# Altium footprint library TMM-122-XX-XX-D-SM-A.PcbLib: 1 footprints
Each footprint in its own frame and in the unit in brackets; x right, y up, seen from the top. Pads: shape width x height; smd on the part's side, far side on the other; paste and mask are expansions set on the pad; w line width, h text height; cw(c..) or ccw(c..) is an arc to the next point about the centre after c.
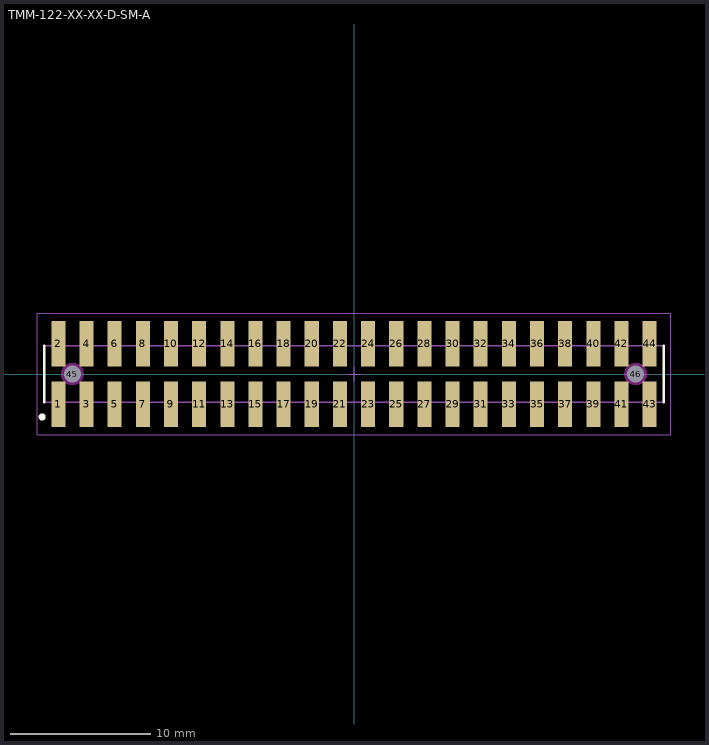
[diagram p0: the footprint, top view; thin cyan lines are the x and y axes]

## TMM-122-XX-XX-D-SM-A [mm] "2.00mm pitch, 44 pin, terminal strip; double row, w/alignment pins, SMT"
height 2.77
pads (46):
  rect 1x3.2 smd mask+0: 1(-21,-2.15) 2(-21,2.15) 3(-19,-2.15) 4(-19,2.15) 5(-17,-2.15) 6(-17,2.15) 7(-15,-2.15) 8(-15,2.15) 9(-13,-2.15) 10(-13,2.15) 11(-11,-2.15) 12(-11,2.15) 13(-9,-2.15) 14(-9,2.15) 15(-7,-2.15) 16(-7,2.15) 17(-5,-2.15) 18(-5,2.15) 19(-3,-2.15) 20(-3,2.15) 21(-1,-2.15) 22(-1,2.15) 23(1,-2.15) 24(1,2.15) 25(3,-2.15) 26(3,2.15) 27(5,-2.15) 28(5,2.15) 29(7,-2.15) 30(7,2.15) 31(9,-2.15) 32(9,2.15) 33(11,-2.15) 34(11,2.15) 35(13,-2.15) 36(13,2.15) 37(15,-2.15) 38(15,2.15) 39(17,-2.15) 40(17,2.15) 41(19,-2.15) 42(19,2.15) 43(21,-2.15) 44(21,2.15)
  round 1 hole 1.2 unplated mask+0: 45(-20,0) 46(20,0)
Top Overlay:
  circle w0.25: c-22.15,-3.05 r0.125
  lines w0.2: -22,-2 -22,2 ; 22,-2 22,2
Keep-Out Layer:
  pour cut-out: -19.193,0 -19.221,0.209 -19.301,0.403 -19.429,0.571 -19.597,0.699 -19.791,0.779 -20,0.807 -20.209,0.779 -20.403,0.699 -20.571,0.571 -20.699,0.403 -20.779,0.209 -20.807,0 -20.779,-0.209 -20.699,-0.403 -20.571,-0.571 -20.403,-0.699 -20.209,-0.779 -20,-0.807 -19.791,-0.779 -19.597,-0.699 -19.429,-0.571 -19.301,-0.403 -19.221,-0.209
  pour cut-out: 20.807,0 20.779,0.209 20.699,0.403 20.571,0.571 20.403,0.699 20.209,0.779 20,0.807 19.791,0.779 19.597,0.699 19.429,0.571 19.301,0.403 19.221,0.209 19.193,0 19.221,-0.209 19.301,-0.403 19.429,-0.571 19.597,-0.699 19.791,-0.779 20,-0.807 20.209,-0.779 20.403,-0.699 20.571,-0.571 20.699,-0.403 20.779,-0.209
Mechanical 12:
  lines w0.001: -22,-2 22,-2 22,2 -22,2 -22,-2
Mechanical 13:
  lines w0.1: -22,-2 22,-2 22,2 -22,2 -22,-2
  text ".Designator" at 0,-0.127 h1.52
Mechanical 15:
  lines w0.05: -0.5,0 0.5,0 ; 0,-0.5 0,0.5 ; -22.5,-4.3 22.5,-4.3 22.5,4.3 -22.5,4.3 -22.5,-4.3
